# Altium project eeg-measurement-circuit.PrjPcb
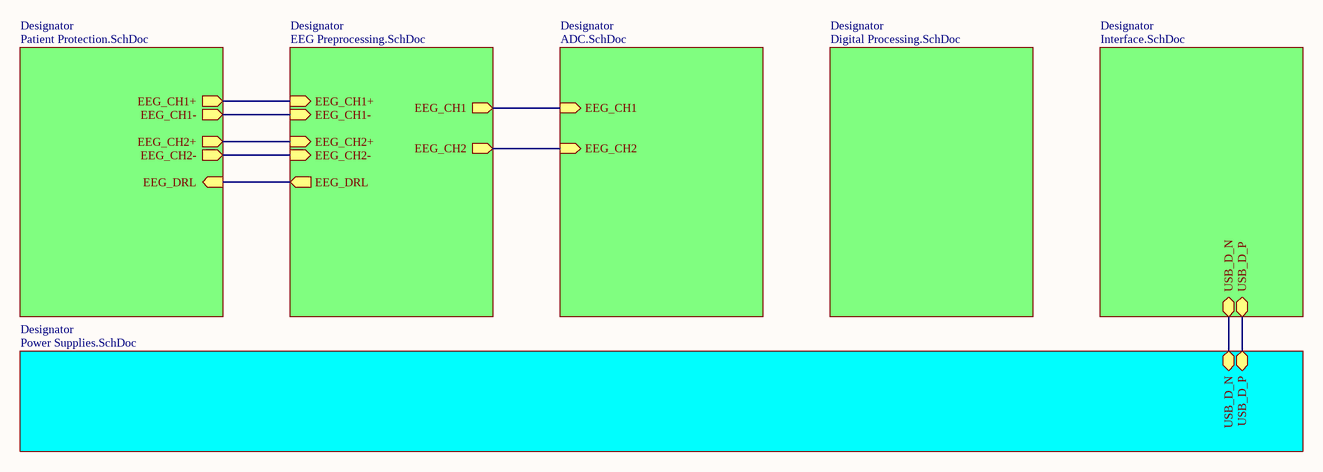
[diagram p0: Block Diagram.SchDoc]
7 sheets, 179 parts. Net scope: hierarchical (ports join the sheet entries above them; power ports are global).
Sheets:
  Block Diagram.SchDoc
    Designator = Power Supplies.SchDoc
    Designator = EEG Preprocessing.SchDoc
    Designator = ADC.SchDoc
    Designator = Digital Processing.SchDoc
    Designator = Interface.SchDoc
    Designator = Patient Protection.SchDoc

## Sheet Block Diagram.SchDoc: EEG Measurement Circuit
size A3; Date: 24/01/2025; DrawnBy: Giang Phan Truong; SheetNumber: 1; SheetTotal: 7

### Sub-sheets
Designator = Power Supplies.SchDoc: USB_D_N (bidir), USB_D_P (bidir)
Designator = EEG Preprocessing.SchDoc: EEG_CH1+ (in), EEG_CH1- (in), EEG_CH2+ (in), EEG_CH2- (in), EEG_CH1 (out), EEG_CH2 (out), EEG_DRL (out)
Designator = ADC.SchDoc: EEG_CH2 (in), EEG_CH1 (in)
Designator = Digital Processing.SchDoc: no entries
Designator = Interface.SchDoc: USB_D_P (bidir), USB_D_N (bidir)
Designator = Patient Protection.SchDoc: EEG_CH1+ (out), EEG_CH1- (out), EEG_CH2- (out), EEG_CH2+ (out), EEG_DRL (in)

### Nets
USB_D_N: sheet Designator/USB_D_N, sheet Designator/USB_D_N
USB_D_P: sheet Designator/USB_D_P, sheet Designator/USB_D_P
NetC?#17_2: sheet Designator/EEG_CH1+, sheet Designator/EEG_CH1+
NetC?#19_2: sheet Designator/EEG_CH1-, sheet Designator/EEG_CH1-
NetC?#39_2: sheet Designator/EEG_CH2+, sheet Designator/EEG_CH2+
NetC?#41_2: sheet Designator/EEG_CH2-, sheet Designator/EEG_CH2-
NetC?#56_2: sheet Designator/EEG_DRL, sheet Designator/EEG_DRL
NetR?#24_2: sheet Designator/EEG_CH1, sheet Designator/EEG_CH1
NetR?#54_2: sheet Designator/EEG_CH2, sheet Designator/EEG_CH2

## Sheet Power Supplies.SchDoc: EEG Measurement Circuit
size A3; Date: 24/01/2025; DrawnBy: Giang Phan Truong; SheetNumber: 2; SheetTotal: 7
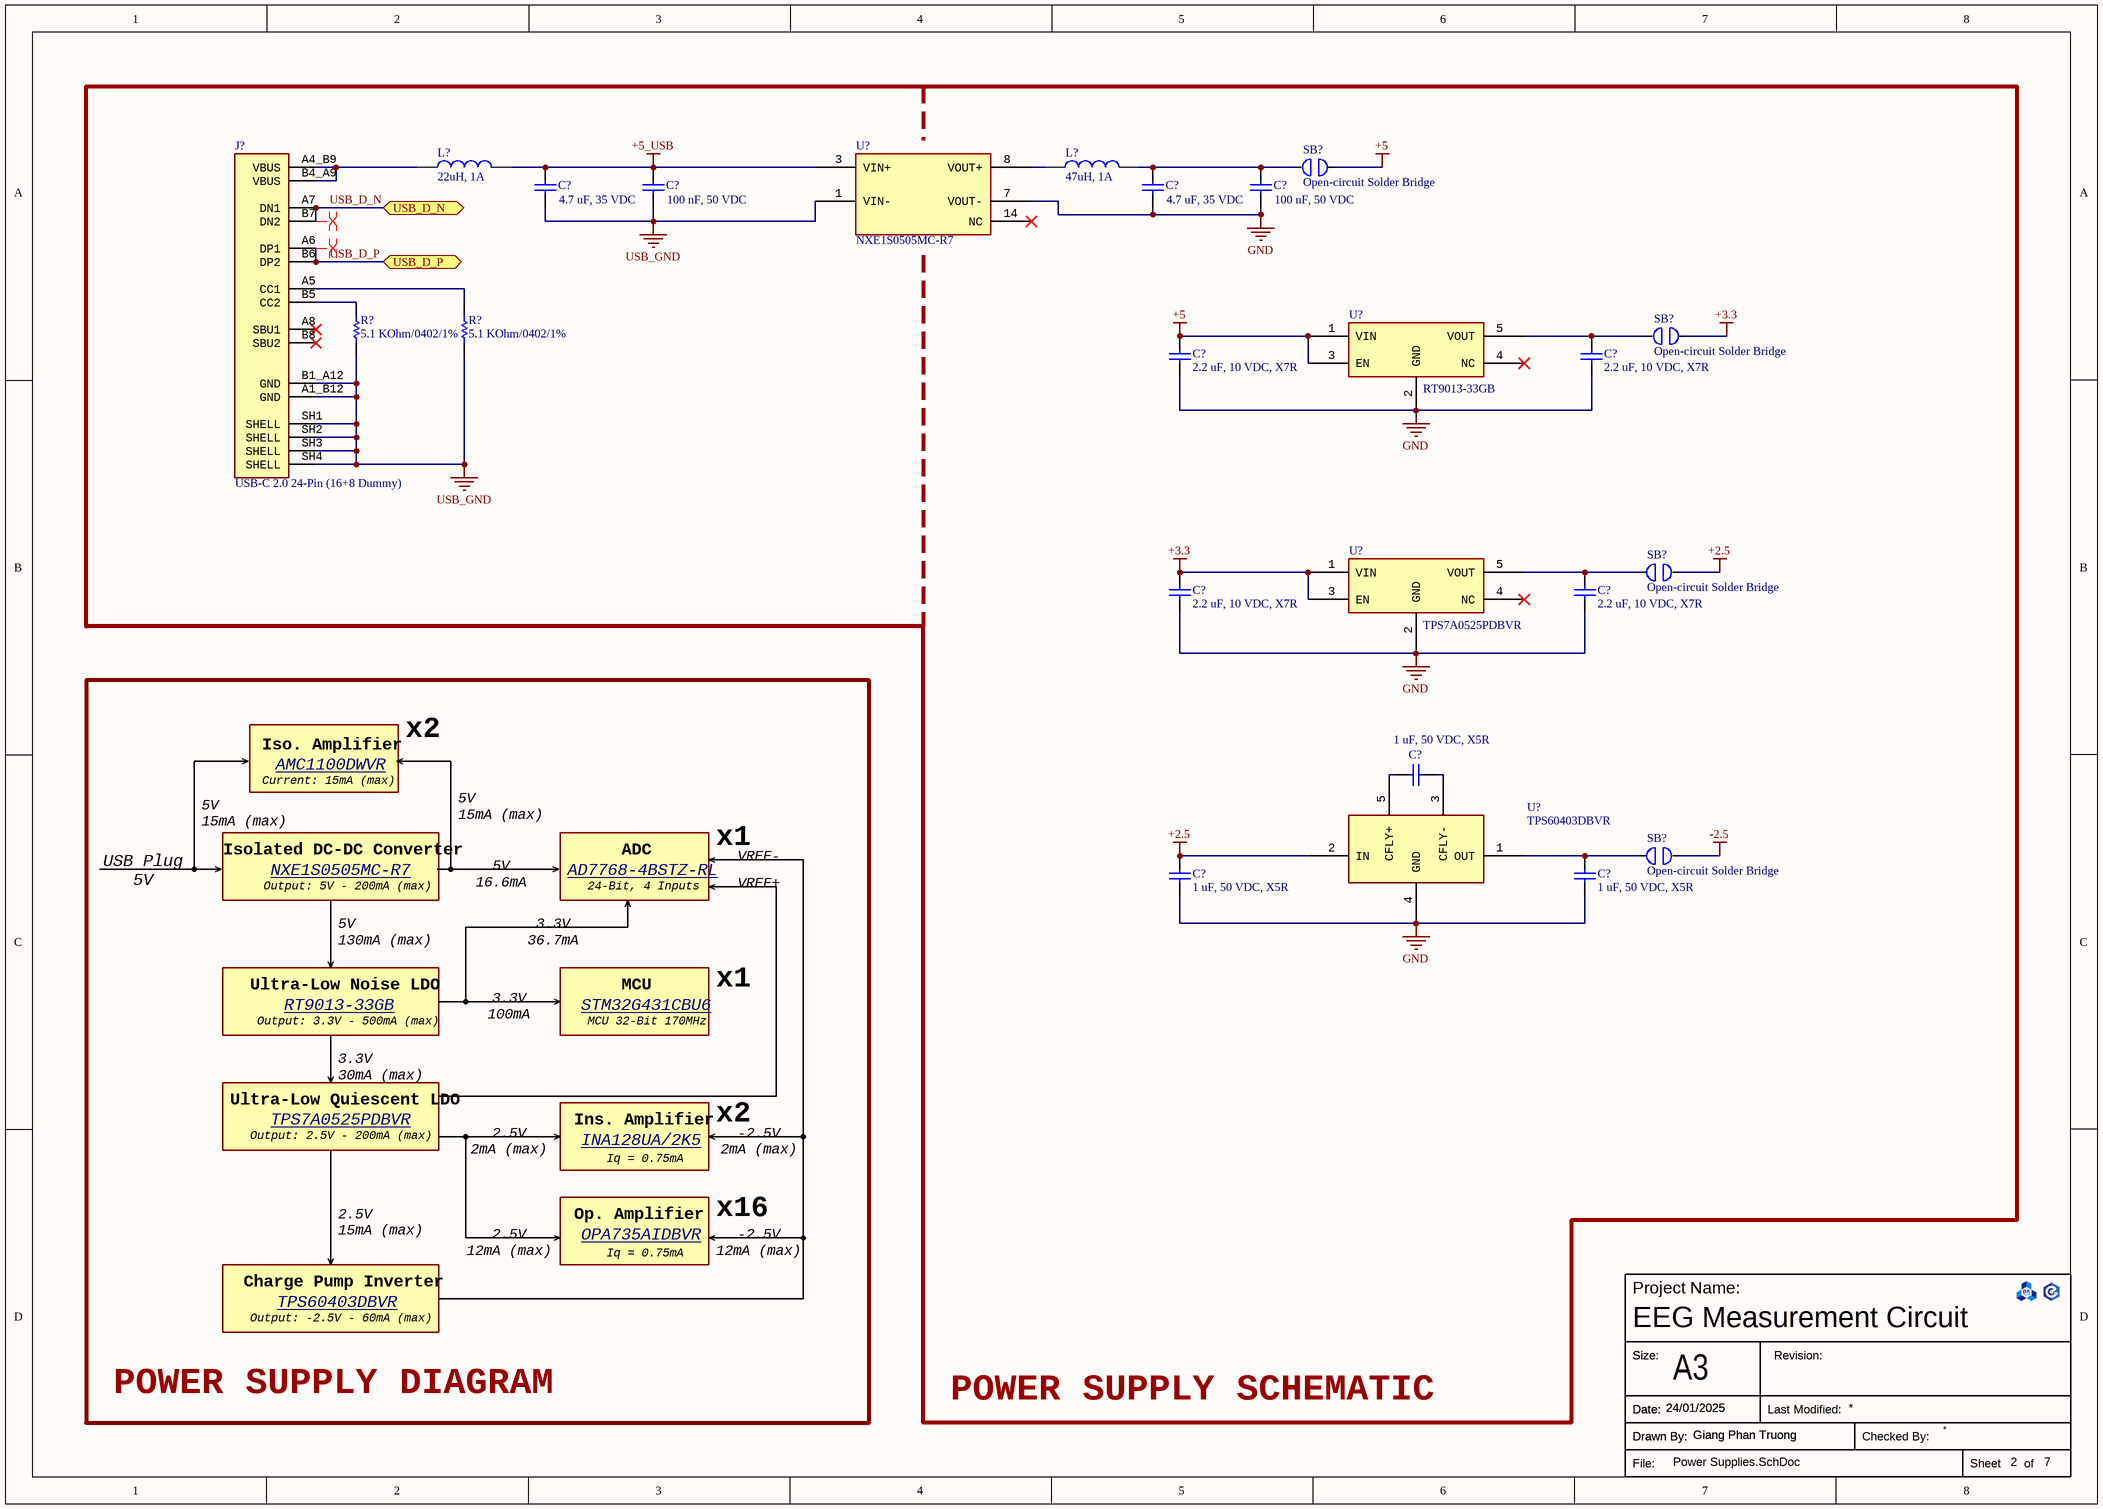
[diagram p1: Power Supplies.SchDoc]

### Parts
(Parts that share a designator on the sheet are numbered #1, #2 ... from top to bottom, then left to right.)
C?#1  4.7 uF, 35 VDC  [CAP_0603]
C?#2  100 nF, 50 VDC  [CAP_0603]
C?#3  4.7 uF, 35 VDC  [CAP_0603]
C?#4  100 nF, 50 VDC  [CAP_0603]
C?#5  2.2 uF, 10 VDC, X7R  [CAP_0603]
C?#6  2.2 uF, 10 VDC, X7R  [CAP_0603]
C?#7  2.2 uF, 10 VDC, X7R  [CAP_0603]
C?#8  2.2 uF, 10 VDC, X7R  [CAP_0603]
C?#9  1 uF, 50 VDC, X5R  [CAP_0603]
C?#10  1 uF, 50 VDC, X5R  [CAP_0603]
C?#11  1 uF, 50 VDC, X5R  [CAP_0603]
J?#1  value USB-C 2.0 24-Pin (16+8 Dummy)  [GCT_USB4105-GF-A]  (hidden comment: USB4105-GF-A)
L?#1  22uH, 1A  [Inductor_CDRH4D28]
L?#2  47uH, 1A  [Inductor_CDRH4D28]
R?#1  value 5.1 KOhm/0402/1%  [R0402]  (hidden comment: Resistor 5.1 KOhm 0402)
R?#2  value 5.1 KOhm/0402/1%  [R0402]  (hidden comment: Resistor 5.1 KOhm 0402)
SB?#1  Open-circuit Solder Bridge  [SolderBridgeOpen]
SB?#2  Open-circuit Solder Bridge  [SolderBridgeOpen]
SB?#3  Open-circuit Solder Bridge  [SolderBridgeOpen]
SB?#4  Open-circuit Solder Bridge  [SolderBridgeOpen]
U?#1  NXE1S0505MC-R7  [NXE1S0505MC_MUR]
U?#2  RT9013-33GB  [SOT-23-5_RIT]
U?#3  TPS7A0525PDBVR  [DBV0005A_L]
U?#4  TPS60403DBVR  [SOT95P280X145-5N]

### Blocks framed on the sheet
POWER SUPPLY SCHEMATIC: C?#1-C?#11 J?#1 L?#1 L?#2 R?#1 R?#2 SB?#1-SB?#4 U?#1-U?#4

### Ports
USB_D_N (bidir, see Block Diagram[7B], Interface[5B]), USB_D_P (bidir, see Block Diagram[7B], Interface[5B])

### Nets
+2.5: C?#10.2 SB?#3.1 U?#4.2(IN)
+3.3: C?#7.2 SB?#2.1 U?#3.1(VIN) U?#3.3(EN)
+5: C?#5.2 SB?#1.1 U?#2.1(VIN) U?#2.3(EN)
+5_USB: C?#1.2 C?#2.2 L?#1.2 U?#1.3(VIN+)
-2.5: SB?#4.1
GND: C?#3.1 C?#4.1 C?#5.1 C?#6.1 C?#7.1 C?#8.1 C?#10.1 C?#11.1 U?#1.7(VOUT-) U?#2.2(GND) U?#3.2(GND) U?#4.4(GND)
USB_GND: C?#1.1 C?#2.1 J?#1.A1_B12(GND) J?#1.B1_A12(GND) J?#1.SH1(SHELL) J?#1.SH2(SHELL) J?#1.SH3(SHELL) J?#1.SH4(SHELL) R?#1.1 R?#2.1 U?#1.1(VIN-)
USB_D_N: J?#1.A7(DN1) J?#1.B7(DN2) ; port USB_D_N
USB_D_P: J?#1.A6(DP1) J?#1.B6(DP2) ; port USB_D_P
NetC?#3_2: C?#3.2 C?#4.2 L?#2.2 SB?#1.2
NetC?#6_2: C?#6.2 SB?#2.2 U?#2.5(VOUT)
NetC?#8_2: C?#8.2 SB?#3.2 U?#3.5(VOUT)
NetC?#9_1: C?#9.1 U?#4.5(CFLY+)
NetC?#9_2: C?#9.2 U?#4.3(CFLY-)
NetC?#11_2: C?#11.2 SB?#4.2 U?#4.1(OUT)
NetJ?#1_A4_B9: J?#1.A4_B9(VBUS) J?#1.B4_A9(VBUS) L?#1.1
NetJ?#1_A5: J?#1.A5(CC1) R?#2.2
NetJ?#1_B5: J?#1.B5(CC2) R?#1.2
NetL?#2_1: L?#2.1 U?#1.8(VOUT+)

Not connected (* = marked no-connect by the designer): J?#1 A8(SBU1)* B8(SBU2)*; U?#1 14(NC)*; U?#2 4(NC)*; U?#3 4(NC)*

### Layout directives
differential pair: USB_D_N, USB_D_P

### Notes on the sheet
- Iso. Amplifier
- Current: 15mA (max)
- AMC1100DWVR <https://www.digikey.com/en/products/detail/texas-instruments/amc1100dwvr/6571602>
- x2
- 5V
  15mA (max)
- Isolated DC-DC Converter
- ADC
- x1
- USB Plug
  5V
- Output: 5V - 200mA (max)
- NXE1S0505MC-R7 <https://www.digikey.com/en/products/detail/murata-power-solutions-inc/NXE1S0505MC-R7/5047366>
- 5V
  16.6mA (max)
- AD7768-4BSTZ-RL <https://www.digikey.com/en/products/detail/analog-devices-inc/AD7768-4BSTZ-RL/6056981>
- 24-Bit, 4 Inputs
- VREF-
- VREF+
- Ultra-Low Noise LDO
- 5V
  130mA (max)
- 3.3V
  36.7mA (max)
- MCU
- Output: 3.3V - 500mA (max)
- RT9013-33GB <https://www.thegioiic.com/rt9013-33gb-ic-on-ap-3-3v-500ma-sot-23-5>
- 3.3V
  100mA (max)
- STM32G431CBU6 <https://www.digikey.com/en/products/detail/stmicroelectronics/STM32G431CBU6/10231569>
- MCU 32-Bit 170MHz
- Ultra-Low Quiescent LDO
- TPS7A0525PDBVR <https://www.digikey.com/en/products/detail/texas-instruments/TPS7A0525PDBVR/9489224>
- 3.3V
  30mA (max)
- Ins. Amplifier
- Output: 2.5V - 200mA (max)
- 2.5V
  2mA (max)
- INA128UA/2K5 <https://www.digikey.com/en/products/detail/texas-instruments/INA128UA-2K5/300998>
- Iq = 0.75mA
- -2.5V
  2mA (max)
- 2.5V
  15mA (max)
- 2.5V
  12mA (max)
- Op. Amplifier
- OPA735AIDBVR <https://www.digikey.com/en/products/detail/texas-instruments/OPA735AIDBVR/1572946>
- x16
- -2.5V
  12mA (max)
- Charge Pump Inverter
- Output: -2.5V - 60mA (max)
- TPS60403DBVR <https://www.digikey.com/en/products/detail/texas-instruments/TPS60403DBVR/1672064>
- POWER SUPPLY DIAGRAM

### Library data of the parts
C?#1 C?#3 = 0106034751035: CAP, size 0603, 4.7 uF, 35 VDC; Manufacture Name: Samsung Electro-Mechanics; Manufacture SN: CL10A475KL8NRNC; Capacitance: 4.7 uF; Tolerance: +/-10%; Voltage Rating DC: 35 VDC
C?#2 C?#4 = 0106031041050: CAP, size 0603, 100 nF, 50 VDC; Manufacture Name: TDK; Manufacture SN: CGA3E3X8R1H104K080AE; Capacitance: 100 nF; Tolerance: +/-10%; Voltage Rating DC: 50 VDC
C?#5-C?#8 = 0106032251010: CAP, size 0603, 2.2 uF, 10 VDC; Manufacture Name: Samsung Electro-Mechanics; Manufacture SN: CL10A225KP8NNWC; Capacitance: 2.2 uF; Tolerance: +/-10%; Voltage Rating DC: 10 VDC
C?#9-C?#11 = 0106031051050: CAP, size 0603, 1 nF, 50 VDC; Manufacture Name: TDK; Manufacture SN: CGA3E3X5R1H105K080AB; Capacitance: 1 nF; Tolerance: +/-10%; Voltage Rating DC: 50 VDC
J?#1 = USB4105-GF-A: USB-C (USB TYPE-C) USB 2.0 Receptacle Connector 24 (16+8 Dummy) Position Surface Mount, Right Angle; Through Hole; MF: {'manufacturer': u'GCT'}
L?#1 = IND_22uH_4D28: 22uH 20% 1A SMD Power Inductor 4.8x4.8x2.8 mm; Supply Name: tme
L?#2 = IND_47uH_4D28: 47uH 20% 1A SMD Power Inductor 4.8x4.8x2.8 mm; Supply Part Number: 22uH 20% 1A SMD Power Inductor 4.8x4.8x2.8 mm; Supply Name: tme
R?#1 R?#2 = Resistor 5.1 KOhm 0402: RC0402FR-135K1L
U?#1 = NXE1S0505MC-R7: Isolated Module DC DC Converter 1 Output 5V 200mA 4.5V - 5.5V Input; Mfr_Name: Murata
U?#2 = RT9013-33GB: Linear Voltage Regulator IC Positive Fixed 1 Output 500mA SOT-23-5; Mfr_Name: Richtek Technology
U?#3 = TPS7A0525PDBVR: Linear Voltage Regulator IC Positive Fixed 1 Output 200mA SOT-23-5; Mfr_Name: Texas Instruments
U?#4 = TPS60403DBVR: 60mA Charge Pump Voltage Inverter with Fixed 250kHz Operation; MF: Texas Instruments

## Sheet EEG Preprocessing.SchDoc: EEG Measurement Circuit
size A2; Date: 24/01/2025; DrawnBy: Giang Phan Truong; SheetNumber: 4; SheetTotal: 7; SPICEModelCacheZASXATAV: <root> / <DocumentId>ZASXATAV</DocumentId> / <CacheFrame Number="0"> / <Model Name="0402_885012105018_100nf" Kind="CKT"> / <Text>******* / .subckt 0402_885012105018_100nF 1 2 / Rser 1 3 0.026120802334 / Lser 2 4 3.09671131E-10 / C1 3 4 0.0000001 / Rpar 3 4 5000000000 / .ends 0402_885012105018_100nF</Text> / </Model> / <Model Name="0402_885012105017_220nf" Kind="CKT"> / <Text>******* / .subckt 0402_885012105017_220nF 1 2 / Rser 1 3 0.0118013539585 / Lser 2 4 3.47460059E-10 / C1 3 4 0.00000022 / Rpar 3 4 500000000 / .ends 0402_885012105017_220nF</Text> / </Model> / <Model Name="1812_885012210006_10nf" Kind="CKT"> / <Text>******* / .subckt 1812_885012210006_10nF 1 2 / Rser 1 3 0.07693 / Lser 2 4 0.00000000053548 / C1 3 4 0.00000001 / Rpar 3 4 10000000000 / .ends 1812_885012210006_10nF</Text> / </Model> / </CacheFrame> / </root>
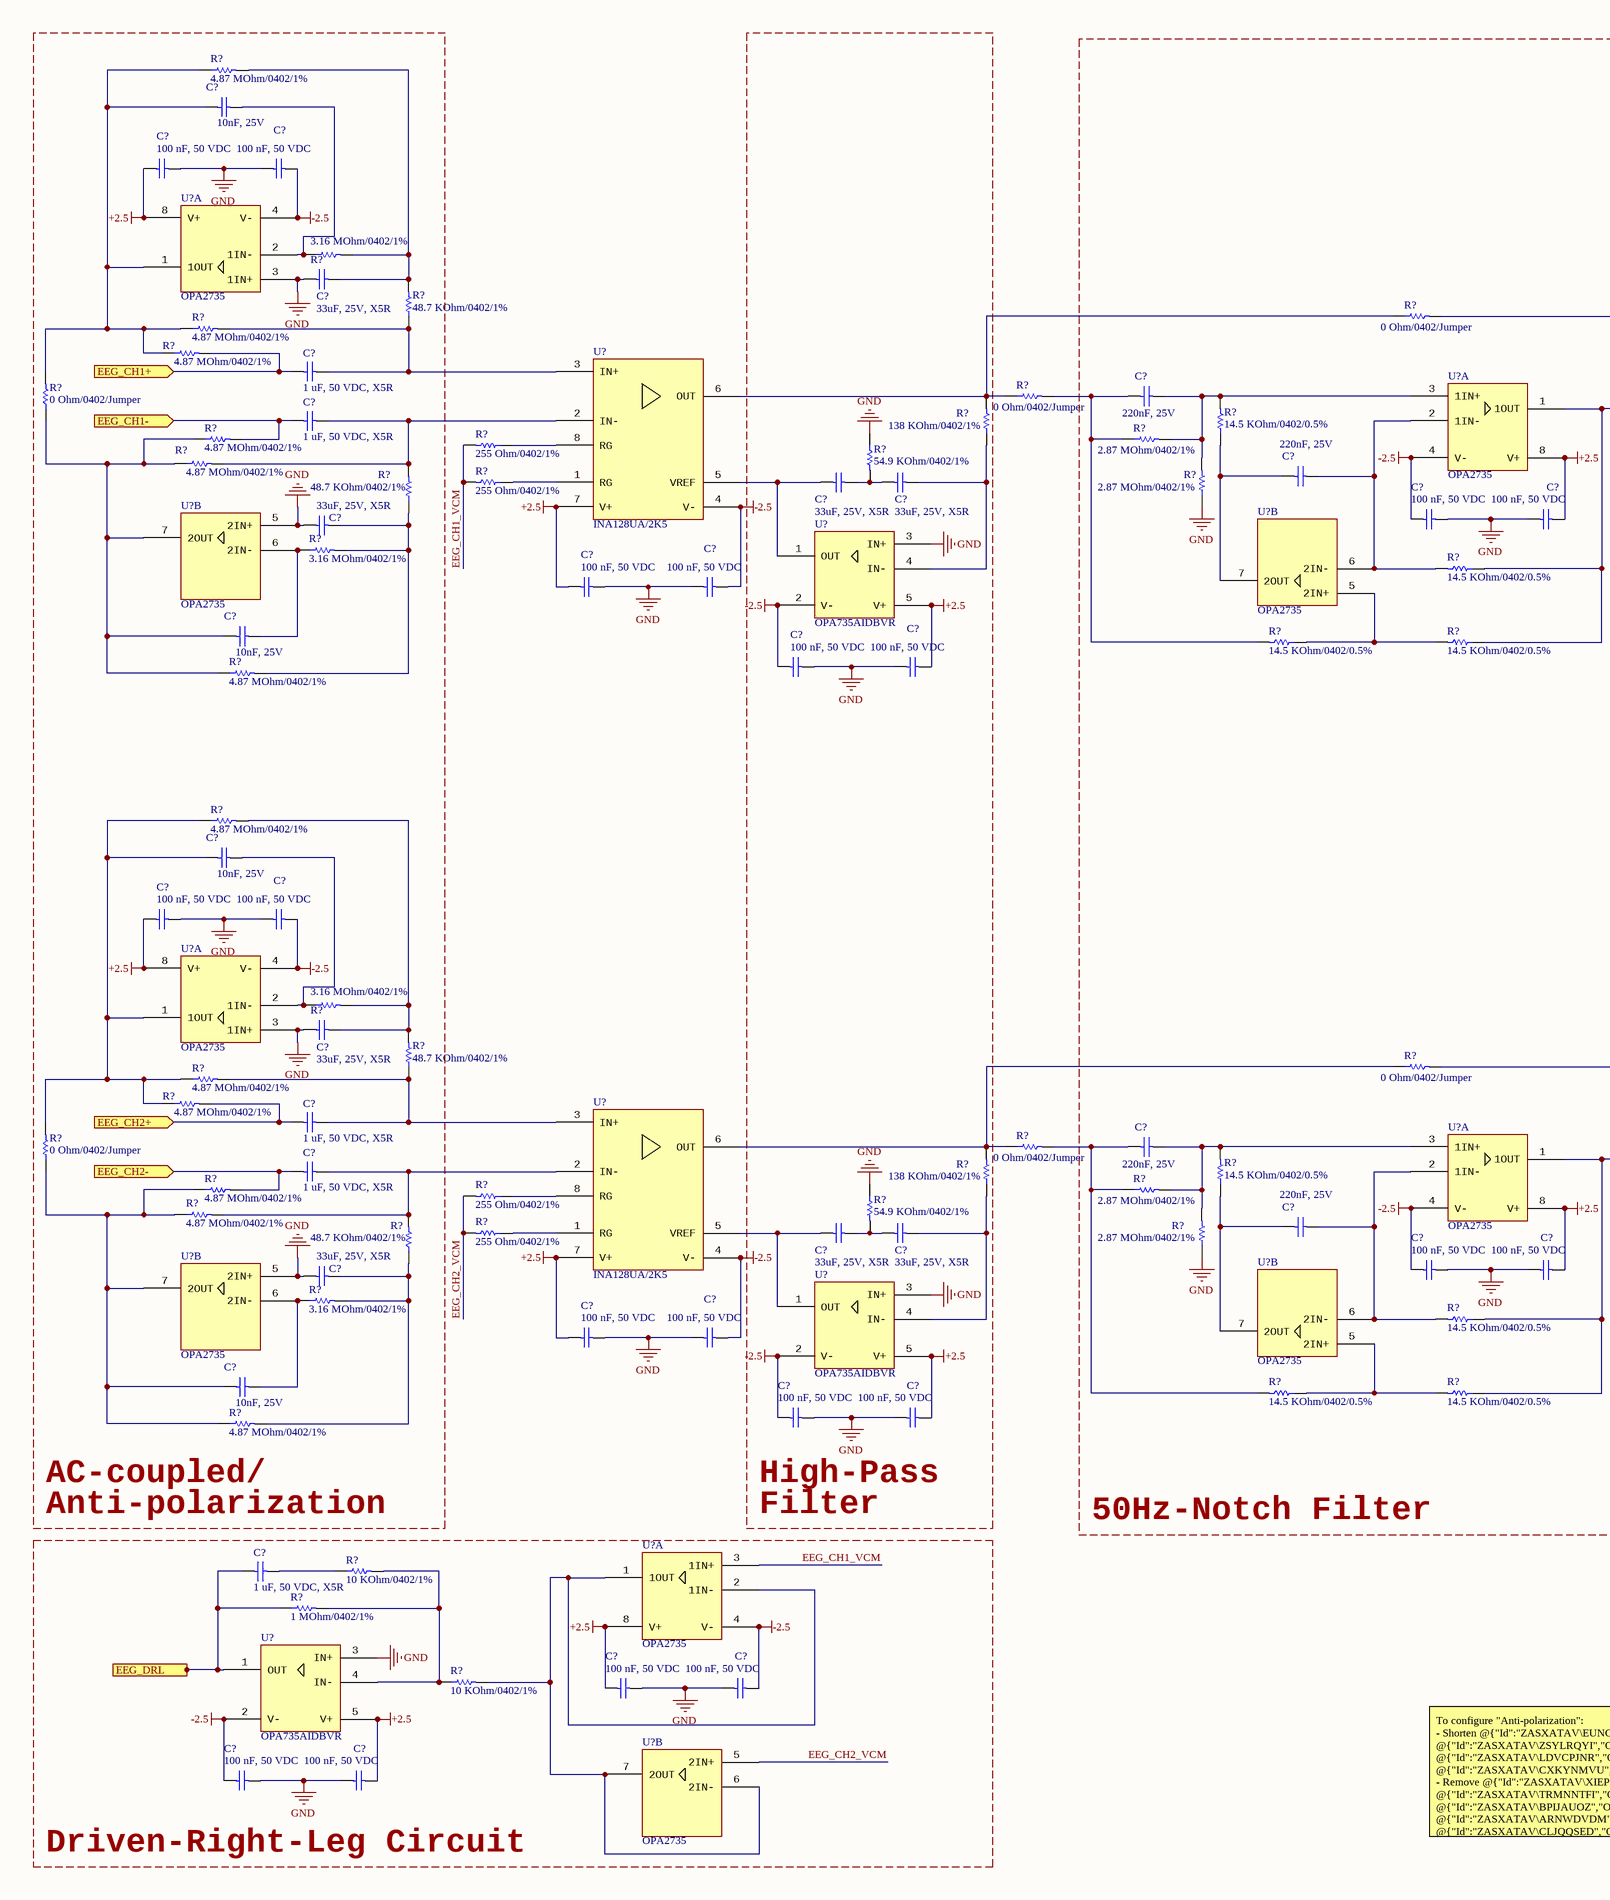
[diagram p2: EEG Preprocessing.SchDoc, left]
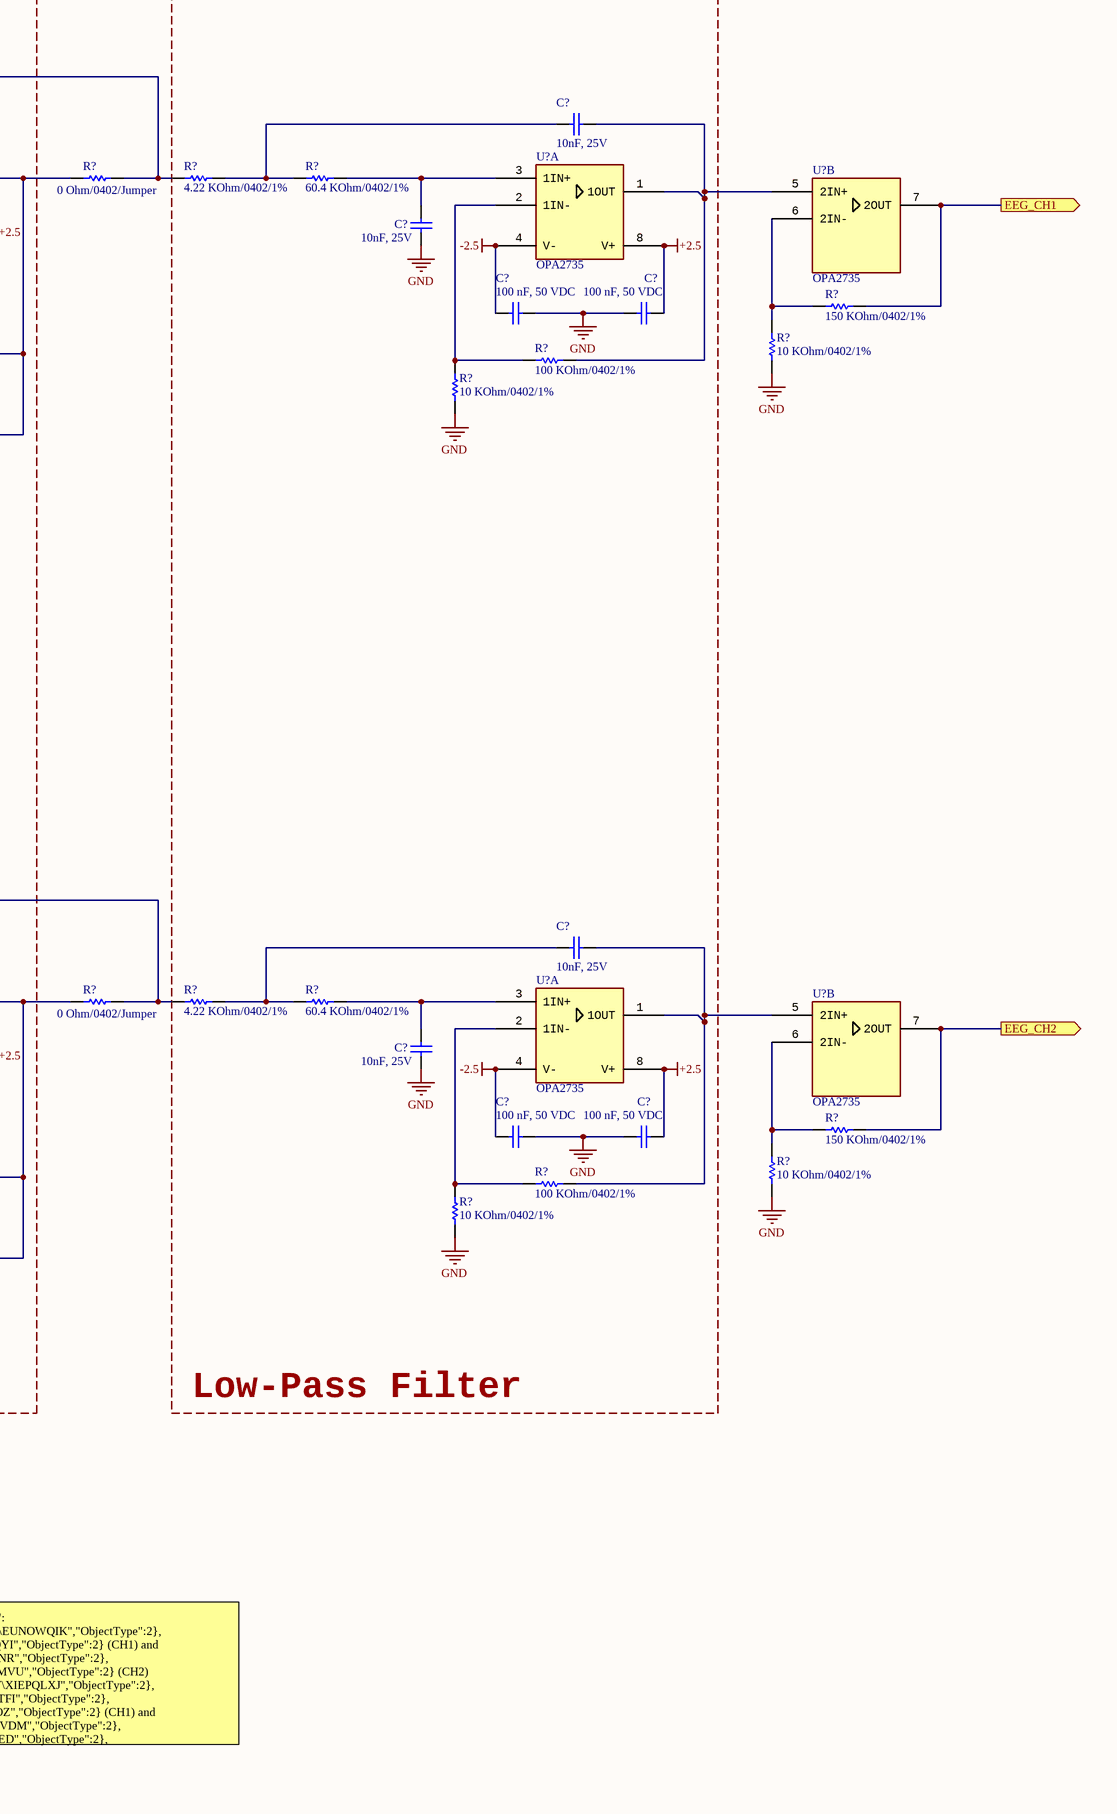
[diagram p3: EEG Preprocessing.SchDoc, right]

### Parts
(Parts that share a designator on the sheet are numbered #1, #2 ... from top to bottom, then left to right.)
C?#12  value 10nF, 25V  [WCAP-CSGP_0402_L1W0.5H0.5]  (hidden comment: 100nF)
C?#13  100 nF, 50 VDC  [CAP_0603]
C?#14  100 nF, 50 VDC  [CAP_0603]
C?#15  value 33uF, 25V, X5R  [WCAP-CSGP_1206_L3.2W1.6H1.6]  (hidden comment: 4.7μF)
C?#16  value 10nF, 25V  [WCAP-CSGP_1812_L4.5W3.2H1.25]  (hidden comment: 10nF)
C?#17  1 uF, 50 VDC, X5R  [CAP_0603]
C?#18  value 220nF, 25V  [WCAP-CSGP_0402_L1W0.5H0.5]  (hidden comment: 220nF)
C?#19  1 uF, 50 VDC, X5R  [CAP_0603]
C?#20  value 10nF, 25V  [WCAP-CSGP_1812_L4.5W3.2H1.25]  (hidden comment: 10nF)
C?#21  value 220nF, 25V  [WCAP-CSGP_0402_L1W0.5H0.5]  (hidden comment: 220nF)
C?#22  value 33uF, 25V, X5R  [WCAP-CSGP_1206_L3.2W1.6H1.6]  (hidden comment: 4.7μF)
C?#23  value 33uF, 25V, X5R  [WCAP-CSGP_1206_L3.2W1.6H1.6]  (hidden comment: 4.7μF)
C?#24  100 nF, 50 VDC  [CAP_0603]
C?#25  100 nF, 50 VDC  [CAP_0603]
C?#26  value 33uF, 25V, X5R  [WCAP-CSGP_1206_L3.2W1.6H1.6]  (hidden comment: 4.7μF)
C?#27  100 nF, 50 VDC  [CAP_0603]
C?#28  100 nF, 50 VDC  [CAP_0603]
C?#29  100 nF, 50 VDC  [CAP_0603]
C?#30  100 nF, 50 VDC  [CAP_0603]
C?#31  value 10nF, 25V  [WCAP-CSGP_0402_L1W0.5H0.5]  (hidden comment: 100nF)
C?#32  100 nF, 50 VDC  [CAP_0603]
C?#33  100 nF, 50 VDC  [CAP_0603]
C?#34  value 10nF, 25V  [WCAP-CSGP_0402_L1W0.5H0.5]  (hidden comment: 100nF)
C?#35  100 nF, 50 VDC  [CAP_0603]
C?#36  100 nF, 50 VDC  [CAP_0603]
C?#37  value 33uF, 25V, X5R  [WCAP-CSGP_1206_L3.2W1.6H1.6]  (hidden comment: 4.7μF)
C?#38  value 10nF, 25V  [WCAP-CSGP_1812_L4.5W3.2H1.25]  (hidden comment: 10nF)
C?#39  1 uF, 50 VDC, X5R  [CAP_0603]
C?#40  value 220nF, 25V  [WCAP-CSGP_0402_L1W0.5H0.5]  (hidden comment: 220nF)
C?#41  1 uF, 50 VDC, X5R  [CAP_0603]
C?#42  value 10nF, 25V  [WCAP-CSGP_1812_L4.5W3.2H1.25]  (hidden comment: 10nF)
C?#43  value 220nF, 25V  [WCAP-CSGP_0402_L1W0.5H0.5]  (hidden comment: 220nF)
C?#44  value 33uF, 25V, X5R  [WCAP-CSGP_1206_L3.2W1.6H1.6]  (hidden comment: 4.7μF)
C?#45  value 33uF, 25V, X5R  [WCAP-CSGP_1206_L3.2W1.6H1.6]  (hidden comment: 4.7μF)
C?#46  100 nF, 50 VDC  [CAP_0603]
C?#47  100 nF, 50 VDC  [CAP_0603]
C?#48  value 33uF, 25V, X5R  [WCAP-CSGP_1206_L3.2W1.6H1.6]  (hidden comment: 4.7μF)
C?#49  100 nF, 50 VDC  [CAP_0603]
C?#50  100 nF, 50 VDC  [CAP_0603]
C?#51  100 nF, 50 VDC  [CAP_0603]
C?#52  100 nF, 50 VDC  [CAP_0603]
C?#53  value 10nF, 25V  [WCAP-CSGP_0402_L1W0.5H0.5]  (hidden comment: 100nF)
C?#54  100 nF, 50 VDC  [CAP_0603]
C?#55  100 nF, 50 VDC  [CAP_0603]
C?#56  1 uF, 50 VDC, X5R  [CAP_0603]
C?#57  100 nF, 50 VDC  [CAP_0603]
C?#58  100 nF, 50 VDC  [CAP_0603]
C?#59  100 nF, 50 VDC  [CAP_0603]
C?#60  100 nF, 50 VDC  [CAP_0603]
R?#3  value 4.87 MOhm/0402/1%  [R0402]  (hidden comment: Resistor 4.87 MOhm 0402 1%)
R?#4  value 3.16 MOhm/0402/1%  [R0402]  (hidden comment: Resistor 3.16 MOhm 0402 1%)
R?#5  value 48.7 KOhm/0402/1%  [R0402]  (hidden comment: Resistor 48.7 KOhm 0402 1%)
R?#6  value 0 Ohm/0402/Jumper  [R0402]  (hidden comment: Resistor 0 Ohm 0402)
R?#7  value 4.87 MOhm/0402/1%  [R0402]  (hidden comment: Resistor 4.87 MOhm 0402 1%)
R?#8  value 4.87 MOhm/0402/1%  [R0402]  (hidden comment: Resistor 4.87 MOhm 0402 1%)
R?#9  value 0 Ohm/0402/Jumper  [R0402]  (hidden comment: Resistor 0 Ohm 0402)
R?#10  value 0 Ohm/0402/Jumper  [R0402]  (hidden comment: Resistor 0 Ohm 0402)
R?#11  value 0 Ohm/0402/Jumper  [R0402]  (hidden comment: Resistor 0 Ohm 0402)
R?#12  value 4.22 KOhm/0402/1%  [R0402]  (hidden comment: Resistor 4.22 KOhm 0402 1%)
R?#13  value 60.4 KOhm/0402/1%  [R0402]  (hidden comment: Resistor 60.4 KOhm 0402 1%)
R?#14  value 138 KOhm/0402/1%  [R0402]  (hidden comment: Resistor 138 KOhm 0402 1%)
R?#15  value 14.5 KOhm/0402/0.5%  [R0402]  (hidden comment: Resistor 14.5 KOhm 0402 0.5%)
R?#16  value 4.87 MOhm/0402/1%  [R0402]  (hidden comment: Resistor 4.87 MOhm 0402 1%)
R?#17  value 2.87 MOhm/0402/1%  [R0402]  (hidden comment: Resistor 2.87 MOhm 0402 1%)
R?#18  value 255 Ohm/0402/1%  [R0402]  (hidden comment: Resistor 255 Ohm 0402 1%)
R?#19  value 54.9 KOhm/0402/1%  [R0402]  (hidden comment: Resistor 54.9 KOhm 0402 1%)
R?#20  value 4.87 MOhm/0402/1%  [R0402]  (hidden comment: Resistor 4.87 MOhm 0402 1%)
R?#21  value 255 Ohm/0402/1%  [R0402]  (hidden comment: Resistor 255 Ohm 0402 1%)
R?#22  value 2.87 MOhm/0402/1%  [R0402]  (hidden comment: Resistor 2.87 MOhm 0402 1%)
R?#23  value 48.7 KOhm/0402/1%  [R0402]  (hidden comment: Resistor 48.7 KOhm 0402 1%)
R?#24  value 150 KOhm/0402/1%  [R0402]  (hidden comment: Resistor 150 KOhm 0402 1%)
R?#25  value 3.16 MOhm/0402/1%  [R0402]  (hidden comment: Resistor 3.16 MOhm 0402 1%)
R?#26  value 10 KOhm/0402/1%  [R0402]  (hidden comment: Resistor 10 KOhm 0402 1%)
R?#27  value 14.5 KOhm/0402/0.5%  [R0402]  (hidden comment: Resistor 14.5 KOhm 0402 0.5%)
R?#28  value 100 KOhm/0402/1%  [R0402]  (hidden comment: Resistor 100 KOhm 0402 1%)
R?#29  value 10 KOhm/0402/1%  [R0402]  (hidden comment: Resistor 10 KOhm 0402 1%)
R?#30  value 14.5 KOhm/0402/0.5%  [R0402]  (hidden comment: Resistor 14.5 KOhm 0402 0.5%)
R?#31  value 14.5 KOhm/0402/0.5%  [R0402]  (hidden comment: Resistor 14.5 KOhm 0402 0.5%)
R?#32  value 4.87 MOhm/0402/1%  [R0402]  (hidden comment: Resistor 4.87 MOhm 0402 1%)
R?#33  value 4.87 MOhm/0402/1%  [R0402]  (hidden comment: Resistor 4.87 MOhm 0402 1%)
R?#34  value 3.16 MOhm/0402/1%  [R0402]  (hidden comment: Resistor 3.16 MOhm 0402 1%)
R?#35  value 48.7 KOhm/0402/1%  [R0402]  (hidden comment: Resistor 48.7 KOhm 0402 1%)
R?#36  value 0 Ohm/0402/Jumper  [R0402]  (hidden comment: Resistor 0 Ohm 0402)
R?#37  value 4.87 MOhm/0402/1%  [R0402]  (hidden comment: Resistor 4.87 MOhm 0402 1%)
R?#38  value 4.87 MOhm/0402/1%  [R0402]  (hidden comment: Resistor 4.87 MOhm 0402 1%)
R?#39  value 0 Ohm/0402/Jumper  [R0402]  (hidden comment: Resistor 0 Ohm 0402)
R?#40  value 0 Ohm/0402/Jumper  [R0402]  (hidden comment: Resistor 0 Ohm 0402)
R?#41  value 0 Ohm/0402/Jumper  [R0402]  (hidden comment: Resistor 0 Ohm 0402)
R?#42  value 4.22 KOhm/0402/1%  [R0402]  (hidden comment: Resistor 4.22 KOhm 0402 1%)
R?#43  value 60.4 KOhm/0402/1%  [R0402]  (hidden comment: Resistor 60.4 KOhm 0402 1%)
R?#44  value 138 KOhm/0402/1%  [R0402]  (hidden comment: Resistor 138 KOhm 0402 1%)
R?#45  value 14.5 KOhm/0402/0.5%  [R0402]  (hidden comment: Resistor 14.5 KOhm 0402 0.5%)
R?#46  value 4.87 MOhm/0402/1%  [R0402]  (hidden comment: Resistor 4.87 MOhm 0402 1%)
R?#47  value 2.87 MOhm/0402/1%  [R0402]  (hidden comment: Resistor 2.87 MOhm 0402 1%)
R?#48  value 255 Ohm/0402/1%  [R0402]  (hidden comment: Resistor 255 Ohm 0402 1%)
R?#49  value 54.9 KOhm/0402/1%  [R0402]  (hidden comment: Resistor 54.9 KOhm 0402 1%)
R?#50  value 4.87 MOhm/0402/1%  [R0402]  (hidden comment: Resistor 4.87 MOhm 0402 1%)
R?#51  value 255 Ohm/0402/1%  [R0402]  (hidden comment: Resistor 255 Ohm 0402 1%)
R?#52  value 2.87 MOhm/0402/1%  [R0402]  (hidden comment: Resistor 2.87 MOhm 0402 1%)
R?#53  value 48.7 KOhm/0402/1%  [R0402]  (hidden comment: Resistor 48.7 KOhm 0402 1%)
R?#54  value 150 KOhm/0402/1%  [R0402]  (hidden comment: Resistor 150 KOhm 0402 1%)
R?#55  value 3.16 MOhm/0402/1%  [R0402]  (hidden comment: Resistor 3.16 MOhm 0402 1%)
R?#56  value 10 KOhm/0402/1%  [R0402]  (hidden comment: Resistor 10 KOhm 0402 1%)
R?#57  value 14.5 KOhm/0402/0.5%  [R0402]  (hidden comment: Resistor 14.5 KOhm 0402 0.5%)
R?#58  value 100 KOhm/0402/1%  [R0402]  (hidden comment: Resistor 100 KOhm 0402 1%)
R?#59  value 10 KOhm/0402/1%  [R0402]  (hidden comment: Resistor 10 KOhm 0402 1%)
R?#60  value 14.5 KOhm/0402/0.5%  [R0402]  (hidden comment: Resistor 14.5 KOhm 0402 0.5%)
R?#61  value 14.5 KOhm/0402/0.5%  [R0402]  (hidden comment: Resistor 14.5 KOhm 0402 0.5%)
R?#62  value 4.87 MOhm/0402/1%  [R0402]  (hidden comment: Resistor 4.87 MOhm 0402 1%)
R?#63  value 10 KOhm/0402/1%  [R0402]  (hidden comment: Resistor 10 KOhm 0402 1%)
R?#64  value 1 MOhm/0402/1%  [R0402]  (hidden comment: Resistor 1 MOhm 0402 1%_1)
R?#65  value 10 KOhm/0402/1%  [R0402]  (hidden comment: Resistor 10 KOhm 0402 1%)
U?#5  value OPA2735  [SOIC-8]  (hidden comment: OPA2735AIDR)  (part A of 2)
U?#6  INA128UA/2K5  [SOIC-8]
U?#7  value OPA2735  [SOIC-8]  (hidden comment: OPA2735AIDR)  (part A of 2)
U?#8  value OPA2735  [SOIC-8]  (hidden comment: OPA2735AIDR)  (part A of 2)
U?#9  value OPA2735  [SOIC-8]  (hidden comment: OPA2735AIDR)  (part B of 2)
U?#10  OPA735AIDBVR  [SOT-23]
U?#11  value OPA2735  [SOIC-8]  (hidden comment: OPA2735AIDR)  (part B of 2)
U?#12  value OPA2735  [SOIC-8]  (hidden comment: OPA2735AIDR)  (part B of 2)
U?#13  value OPA2735  [SOIC-8]  (hidden comment: OPA2735AIDR)  (part A of 2)
U?#14  INA128UA/2K5  [SOIC-8]
U?#15  value OPA2735  [SOIC-8]  (hidden comment: OPA2735AIDR)  (part A of 2)
U?#16  value OPA2735  [SOIC-8]  (hidden comment: OPA2735AIDR)  (part A of 2)
U?#17  value OPA2735  [SOIC-8]  (hidden comment: OPA2735AIDR)  (part B of 2)
U?#18  OPA735AIDBVR  [SOT-23]
U?#19  value OPA2735  [SOIC-8]  (hidden comment: OPA2735AIDR)  (part B of 2)
U?#20  value OPA2735  [SOIC-8]  (hidden comment: OPA2735AIDR)  (part B of 2)
U?#21  value OPA2735  [SOIC-8]  (hidden comment: OPA2735AIDR)  (part A of 2)
U?#22  OPA735AIDBVR  [SOT-23]
U?#23  value OPA2735  [SOIC-8]  (hidden comment: OPA2735AIDR)  (part B of 2)

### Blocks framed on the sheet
50Hz-Notch Filter: C?#18 C?#21 C?#24 C?#25 C?#40 C?#43 C?#46 C?#47 R?#6 R?#15 R?#17 R?#22 R?#27 R?#30 R?#31 R?#36 R?#45 R?#47 R?#52 R?#57 R?#60 R?#61 U?#7 U?#12 U?#15 U?#20
Low-Pass Filter: C?#16 C?#20 C?#27 C?#28 C?#38 C?#42 C?#49 C?#50 R?#12 R?#13 R?#28 R?#29 R?#42 R?#43 R?#58 R?#59 U?#8 U?#16
Driven-Right-Leg Circuit: C?#56-C?#60 R?#63-R?#65 U?#21-U?#23

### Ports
EEG_CH1 (out, see Block Diagram[4B], ADC[1B]), EEG_CH1+ (in, see Block Diagram[3B], Patient Protection[6A]), EEG_CH1- (in, see Block Diagram[3B], Patient Protection[6B]), EEG_CH2 (out, see Block Diagram[4B], ADC[1B]), EEG_CH2+ (in, see Block Diagram[3B], Patient Protection[6B]), EEG_CH2- (in, see Block Diagram[3B], Patient Protection[6C]), EEG_DRL (out, see Block Diagram[3B], Patient Protection[4D])

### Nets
+2.5: C?#13.2 C?#25.1 C?#28.1 C?#29.2 C?#33.1 C?#35.2 C?#47.1 C?#50.1 C?#51.2 C?#55.1 C?#57.2 C?#60.1 U?#5.8(V+) U?#6.7(V+) U?#7.8(V+) U?#8.8(V+) U?#10.5(V+) U?#13.8(V+) U?#14.7(V+) U?#15.8(V+) U?#16.8(V+) U?#18.5(V+) U?#21.8(V+) U?#22.5(V+)
-2.5: C?#14.1 C?#24.2 C?#27.2 C?#30.1 C?#32.2 C?#36.1 C?#46.2 C?#49.2 C?#52.1 C?#54.2 C?#58.1 C?#59.2 U?#5.4(V-) U?#6.4(V-) U?#7.4(V-) U?#8.4(V-) U?#10.2(V-) U?#13.4(V-) U?#14.4(V-) U?#15.4(V-) U?#16.4(V-) U?#18.2(V-) U?#21.4(V-) U?#22.2(V-)
GND: C?#13.1 C?#14.2 C?#15.2 C?#20.1 C?#24.1 C?#25.2 C?#26.2 C?#27.1 C?#28.2 C?#29.1 C?#30.2 C?#32.1 C?#33.2 C?#35.1 C?#36.2 C?#37.2 C?#42.1 C?#46.1 C?#47.2 C?#48.2 C?#49.1 C?#50.2 C?#51.1 C?#52.2 C?#54.1 C?#55.2 C?#57.1 C?#58.2 C?#59.1 C?#60.2 R?#19.1 R?#22.1 R?#26.1 R?#29.1 R?#49.1 R?#52.1 R?#56.1 R?#59.1 U?#5.3(1IN+) U?#10.3(IN+) U?#11.5(2IN+) U?#13.3(1IN+) U?#18.3(IN+) U?#19.5(2IN+) U?#22.3(IN+)
EEG_CH1_VCM: R?#18.2 R?#21.2 U?#21.3(1IN+)
EEG_CH2_VCM: R?#48.2 R?#51.2 U?#23.5(2IN+)
NetC?#12_1: C?#12.1 R?#3.1 R?#7.1 R?#8.1 R?#9.2 U?#5.1(1OUT)
NetC?#12_2: C?#12.2 R?#4.1 U?#5.2(1IN-)
NetC?#15_1: C?#15.1 R?#3.2 R?#4.2 R?#5.2
NetC?#16_1: C?#16.1 R?#12.2 R?#13.1
NetC?#16_2: C?#16.2 R?#28.2 U?#8.1(1OUT) U?#9.5(2IN+)
NetC?#17_1: C?#17.1 R?#5.1 R?#7.2 U?#6.3(IN+)
NetC?#17_2: C?#17.2 R?#8.2 ; port EEG_CH1+
NetC?#18_1: C?#18.1 R?#10.2 R?#17.1 R?#30.2
NetC?#18_2: C?#18.2 R?#15.2 R?#17.2 R?#22.2 U?#7.3(1IN+)
NetC?#19_1: C?#19.1 R?#20.2 R?#23.2 U?#6.2(IN-)
NetC?#19_2: C?#19.2 R?#16.2 ; port EEG_CH1-
NetC?#20_2: C?#20.2 R?#13.2 U?#8.3(1IN+)
NetC?#21_1: C?#21.1 R?#15.1 U?#12.7(2OUT)
NetC?#21_2: C?#21.2 R?#27.2 U?#7.2(1IN-) U?#12.6(2IN-)
NetC?#22_1: C?#22.1 C?#23.2 R?#19.2
NetC?#22_2: C?#22.2 U?#6.5(VREF) U?#10.1(OUT)
NetC?#23_1: C?#23.1 R?#14.1 U?#10.4(IN-)
NetC?#26_1: C?#26.1 R?#23.1 R?#25.2 R?#32.2
NetC?#31_1: C?#31.1 R?#9.1 R?#16.1 R?#20.1 R?#32.1 U?#11.7(2OUT)
NetC?#31_2: C?#31.2 R?#25.1 U?#11.6(2IN-)
NetC?#34_1: C?#34.1 R?#33.1 R?#37.1 R?#38.1 R?#39.2 U?#13.1(1OUT)
NetC?#34_2: C?#34.2 R?#34.1 U?#13.2(1IN-)
NetC?#37_1: C?#37.1 R?#33.2 R?#34.2 R?#35.2
NetC?#38_1: C?#38.1 R?#42.2 R?#43.1
NetC?#38_2: C?#38.2 R?#58.2 U?#16.1(1OUT) U?#17.5(2IN+)
NetC?#39_1: C?#39.1 R?#35.1 R?#37.2 U?#14.3(IN+)
NetC?#39_2: C?#39.2 R?#38.2 ; port EEG_CH2+
NetC?#40_1: C?#40.1 R?#40.2 R?#47.1 R?#60.2
NetC?#40_2: C?#40.2 R?#45.2 R?#47.2 R?#52.2 U?#15.3(1IN+)
NetC?#41_1: C?#41.1 R?#50.2 R?#53.2 U?#14.2(IN-)
NetC?#41_2: C?#41.2 R?#46.2 ; port EEG_CH2-
NetC?#42_2: C?#42.2 R?#43.2 U?#16.3(1IN+)
NetC?#43_1: C?#43.1 R?#45.1 U?#20.7(2OUT)
NetC?#43_2: C?#43.2 R?#57.2 U?#15.2(1IN-) U?#20.6(2IN-)
NetC?#44_1: C?#44.1 C?#45.2 R?#49.2
NetC?#44_2: C?#44.2 U?#14.5(VREF) U?#18.1(OUT)
NetC?#45_1: C?#45.1 R?#44.1 U?#18.4(IN-)
NetC?#48_1: C?#48.1 R?#53.1 R?#55.2 R?#62.2
NetC?#53_1: C?#53.1 R?#39.1 R?#46.1 R?#50.1 R?#62.1 U?#19.7(2OUT)
NetC?#53_2: C?#53.2 R?#55.1 U?#19.6(2IN-)
NetC?#56_1: C?#56.1 R?#63.1
NetC?#56_2: C?#56.2 R?#64.1 U?#22.1(OUT) ; port EEG_DRL
NetR?#6_1: R?#6.1 R?#10.1 R?#14.2 U?#6.6(OUT)
NetR?#6_2: R?#6.2 R?#11.2 R?#12.1
NetR?#11_1: R?#11.1 R?#27.1 R?#31.1 U?#7.1(1OUT)
NetR?#18_1: R?#18.1 U?#6.8(RG)
NetR?#21_1: R?#21.1 U?#6.1(RG)
NetR?#24_1: R?#24.1 R?#26.2 U?#9.6(2IN-)
NetR?#24_2: R?#24.2 U?#9.7(2OUT) ; port EEG_CH1
NetR?#28_1: R?#28.1 R?#29.2 U?#8.2(1IN-)
NetR?#30_1: R?#30.1 R?#31.2 U?#12.5(2IN+)
NetR?#36_1: R?#36.1 R?#40.1 R?#44.2 U?#14.6(OUT)
NetR?#36_2: R?#36.2 R?#41.2 R?#42.1
NetR?#41_1: R?#41.1 R?#57.1 R?#61.1 U?#15.1(1OUT)
NetR?#48_1: R?#48.1 U?#14.8(RG)
NetR?#51_1: R?#51.1 U?#14.1(RG)
NetR?#54_1: R?#54.1 R?#56.2 U?#17.6(2IN-)
NetR?#54_2: R?#54.2 U?#17.7(2OUT) ; port EEG_CH2
NetR?#58_1: R?#58.1 R?#59.2 U?#16.2(1IN-)
NetR?#60_1: R?#60.1 R?#61.2 U?#20.5(2IN+)
NetR?#63_2: R?#63.2 R?#64.2 R?#65.1 U?#22.4(IN-)
NetR?#65_2: R?#65.2 U?#21.1(1OUT) U?#21.2(1IN-) U?#23.6(2IN-) U?#23.7(2OUT)

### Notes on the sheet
- (near R?#62) AC-coupled/
- (near C?#54) High-Pass
- Anti-polarization
- Filter
- To configure "Anti-polarization":
  - Shorten @{"Id":"ZASXATAV\EUNOWQIK","ObjectType":2}, @{"Id":"ZASXATAV\ZSYLRQYI","ObjectType":2} (CH1) and @{"Id":"ZASXATAV\LDVCPJNR","ObjectType":2}, @{"Id":"ZASXATAV\CXKYNMVU","ObjectType":2} (CH2)
  - Remove @{"Id":"ZASXATAV\XIEPQLXJ","ObjectType":2}, @{"Id":"ZASXATAV\TRMNNTFI","ObjectType":2}, @{"Id":"ZASXATAV\BPIJAUOZ","ObjectType":2} (CH1) and @{"Id":"ZASXATAV\ARNWDVDM","ObjectType":2}, @{"Id":"ZASXATAV\CLJQQSED","ObjectType":2}, @{"Id":"ZASXATAV\HUWLBNUI","ObjectType":2} (CH2)
  To configure "AC-coupled":
  - Remove @{"Id":"ZASXATAV\DEMCHMGK","ObjectType":2}, @{"Id":"ZASXATAV\FORZWMRQ","ObjectType":2}

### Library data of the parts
C?#12 C?#31 C?#34 C?#53 = 885012105018: 0402 10nF 25V; Manufacturer: Wurth Elektronik; Match Code: WCAP-CSGP; Case/Size Code: 0402; Capacitance Tolerance: +/-20%; Ceramic Type: X5R; Dissipation Factor: 10%; Insulation Resistance: 5GΩ; Technical Reference: X5R0402104M025DFCT10000
C?#13 C?#14 C?#24 C?#25 C?#27-C?#30 C?#32 C?#33 C?#35 C?#36 C?#46 C?#47 C?#49-C?#52 C?#54 C?#55 C?#57-C?#60 = 0106031041050: as C?#2 on sheet Power Supplies
C?#15 C?#22 C?#23 C?#26 C?#37 C?#44 C?#45 C?#48 = 885012108020: 25V 33uF X5R ±20% 1206 Multilayer Ceramic Capacitors MLCC - SMD/SMT ROHS; Manufacturer: Wurth Elektronik; Match Code: WCAP-CSGP; Case/Size Code: 1206; Capacitance Tolerance: +/-20%; Dissipation Factor: 7%; Insulation Resistance: 0.1GΩ; Technical Reference: X5R1206475M025DFCT10000
C?#16 C?#20 C?#38 C?#42 = 885012210006: WCAP-CSGP Multilayer Ceramic Chip Capacitor, General Purpose, size 1812, X7R, 10nF, 25V; Manufacturer: Wurth Elektronik; Case/Size Code: 1812; Capacitance Tolerance: +/-10%; Dissipation Factor: 3.5%; Insulation Resistance: 10GΩ; Technical Reference: X7R1812103K025DFCT10000
C?#17 C?#19 C?#39 C?#41 C?#56 = 0106031051050: as C?#9 on sheet Power Supplies
C?#18 C?#21 C?#40 C?#43 = 885012105017: WCAP-CSGP Multilayer Ceramic Chip Capacitor, General Purpose, size 0402, X5R, 220nF, 16V; Manufacturer: Wurth Elektronik; Case/Size Code: 0402; Capacitance Tolerance: +/-20%; Dissipation Factor: 10%; Insulation Resistance: 0.5GΩ; Technical Reference: X5R0402224M016DFCT10000
R?#3 R?#7 R?#8 R?#16 R?#20 R?#32 R?#33 R?#37 R?#38 R?#46 R?#50 R?#62 = Resistor 4.87 MOhm 0402 1%: 4.87 MOhms ±1% 0.063W, 1/16W Chip Resistor 0402 (1005 Metric) Moisture Resistant Thick Film
R?#4 R?#25 R?#34 R?#55 = Resistor 3.16 MOhm 0402 1%: 3.16 MOhms ±1% 0.063W, 1/16W Chip Resistor 0402 (1005 Metric) Automotive AEC-Q200 Thick Film
R?#5 R?#23 R?#35 R?#53 = Resistor 48.7 KOhm 0402 1%: 48.7 kOhms ±1% 0.063W, 1/16W Chip Resistor 0402 (1005 Metric) Automotive AEC-Q200, Moisture Resistant Thick Film
R?#6 R?#9-R?#11 R?#36 R?#39-R?#41 = Resistor 0 Ohm 0402: 0 Ohms Jumper Chip Resistor 0402 (1005 Metric) Moisture Resistant Thick Film
R?#12 R?#42 = Resistor 4.22 KOhm 0402 1%: 4.22 kOhms ±1% 0.1W, 1/10W Chip Resistor 0402 (1005 Metric) Automotive AEC-Q200 Thick Film
R?#13 R?#43 = Resistor 60.4 KOhm 0402 1%: 60.4 kOhms ±1% 0.063W, 1/16W Chip Resistor 0402 (1005 Metric) Moisture Resistant Thick Film
R?#14 R?#44 = Resistor 138 KOhm 0402 1%: 138 kOhms ±1% 0.1W, 1/10W Chip Resistor 0402 (1005 Metric) Automotive AEC-Q200, Moisture Resistant Thin Film
R?#15 R?#27 R?#30 R?#31 R?#45 R?#57 R?#60 R?#61 = Resistor 14.5 KOhm 0402 0.5%: 14.5 kOhms ±0.5% 0.063W, 1/16W Chip Resistor 0402 (1005 Metric) Thin Film
R?#17 R?#22 R?#47 R?#52 = Resistor 2.87 MOhm 0402 1%: 2.87 MOhms ±1% 0.063W, 1/16W Chip Resistor 0402 (1005 Metric) Automotive AEC-Q200 Thick Film
R?#18 R?#21 R?#48 R?#51 = Resistor 255 Ohm 0402 1%: 255 Ohms ±1% 0.1W, 1/10W Chip Resistor 0402 (1005 Metric) Automotive AEC-Q200 Thick Film
R?#19 R?#49 = Resistor 54.9 KOhm 0402 1%: 138 kOhms ±1% 0.1W, 1/10W Chip Resistor 0402 (1005 Metric) Automotive AEC-Q200, Moisture Resistant Thin Film
R?#24 R?#54 = Resistor 150 KOhm 0402 1%: Code 1503 ,1/16W 1%
R?#26 R?#29 R?#56 R?#59 R?#63 R?#65 = Resistor 10 KOhm 0402 1%: Code 103, 1/16W 1%
R?#28 R?#58 = Resistor 100 KOhm 0402 1%: Code 104, 1/16W 1%
R?#64 = Resistor 1 MOhm 0402 1%_1: Code 105, 1/16W 1%
U?#5 U?#7-U?#9 U?#11-U?#13 U?#15-U?#17 U?#19-U?#21 U?#23 = OPA2735AIDR: 0.05μV/°C max, Single-Supply CMOS Operational Amplifiers Zero-drift Series
U?#6 U?#14 = INA128UA/2K5: Precision, Low Power Instrumentation Amplifiers
U?#10 U?#18 U?#22 = OPA735AIDBVR: Zero-Drift Amplifier 1 Circuit Rail-to-Rail SOT-23-5; Mfr_Name: Texas Instruments

## Sheet ADC.SchDoc: EEG Measurement Circuit
size A2; Date: 24/01/2025; DrawnBy: Giang Phan Truong; SheetNumber: 5; SheetTotal: 7
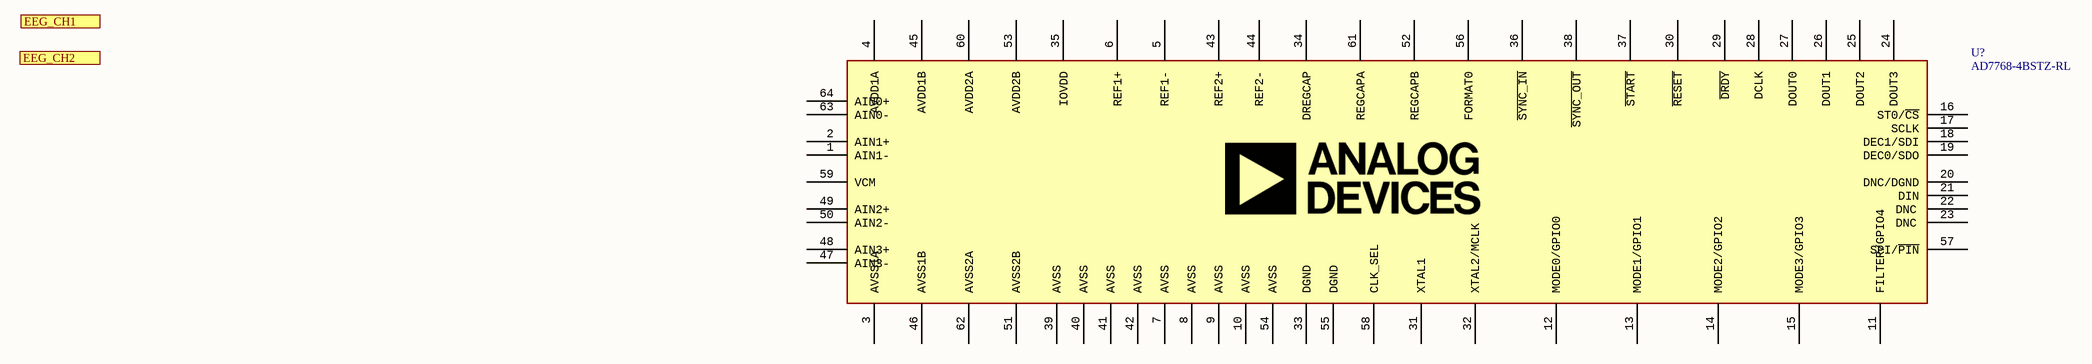
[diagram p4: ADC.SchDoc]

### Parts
(Parts that share a designator on the sheet are numbered #1, #2 ... from top to bottom, then left to right.)
U?#24  value AD7768-4BSTZ-RL  [ST-64-2_ADI]  (hidden comment: 24 Bit Analog to Digital Converter 4 Input 4 Sigma-Delta)

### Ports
EEG_CH1 (out, see Block Diagram[4B], EEG Preprocessing[8A]), EEG_CH2 (out, see Block Diagram[4B], EEG Preprocessing[8C])

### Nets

Not connected (* = marked no-connect by the designer): U?#24 1(AIN1-) 2(AIN1+) 3(AVSS1A) 4(AVDD1A) 5(REF1-) 6(REF1+) 7(AVSS) 8(AVSS) 9(AVSS) 10(AVSS) 11(FILTER/GPIO4) 12(MODE0/GPIO0) 13(MODE1/GPIO1) 14(MODE2/GPIO2) 15(MODE3/GPIO3) 16(ST0/~{CS}) 17(SCLK) 18(DEC1/SDI) 19(DEC0/SDO) 20(DNC/DGND) 21(DIN) 22(DNC) 23(DNC) 24(DOUT3) 25(DOUT2) 26(DOUT1) 27(DOUT0) 28(DCLK) 29(~{DRDY}) 30(~{RESET}) 31(XTAL1) 32(XTAL2/MCLK) 33(DGND) 34(DREGCAP) 35(IOVDD) 36(~{SYNC_IN}) 37(~{START}) 38(~{SYNC_OUT}) 39(AVSS) 40(AVSS) 41(AVSS) 42(AVSS) 43(REF2+) 44(REF2-) 45(AVDD1B) 46(AVSS1B) 47(AIN3-) 48(AIN3+) 49(AIN2+) 50(AIN2-) 51(AVSS2B) 52(REGCAPB) 53(AVDD2B) 54(AVSS) 55(DGND) 56(FORMAT0) 57(SPI/~{PIN}) 58(CLK_SEL) 59(VCM) 60(AVDD2A) 61(REGCAPA) 62(AVSS2A) 63(AIN0-) 64(AIN0+)

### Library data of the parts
U?#24 = AD7768-4BSTZ-RL: 24 Bit Analog to Digital Converter 4 Input 4 Sigma-Delta 64-LQFP (10x10); Mfr_Name: Analog Devices Inc

## Sheet Digital Processing.SchDoc: EEG Measurement Circuit
size A3; Date: 24/01/2025; DrawnBy: Giang Phan Truong; SheetNumber: 7; SheetTotal: 8

## Sheet Interface.SchDoc: EEG Measurement Circuit
size A3; Date: 24/01/2025; DrawnBy: Giang Phan Truong; SheetNumber: 7; SheetTotal: 7
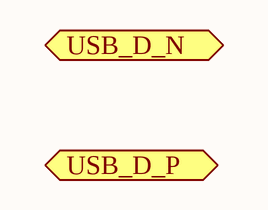
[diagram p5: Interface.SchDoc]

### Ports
USB_D_N (bidir, see Block Diagram[7B], Power Supplies[2A]), USB_D_P (bidir, see Block Diagram[7B], Power Supplies[2A])

## Sheet Patient Protection.SchDoc: EEG Measurement Circuit
size A3; Date: 24/01/2025; DrawnBy: Giang Phan Truong; SheetNumber: 3; SheetTotal: 7
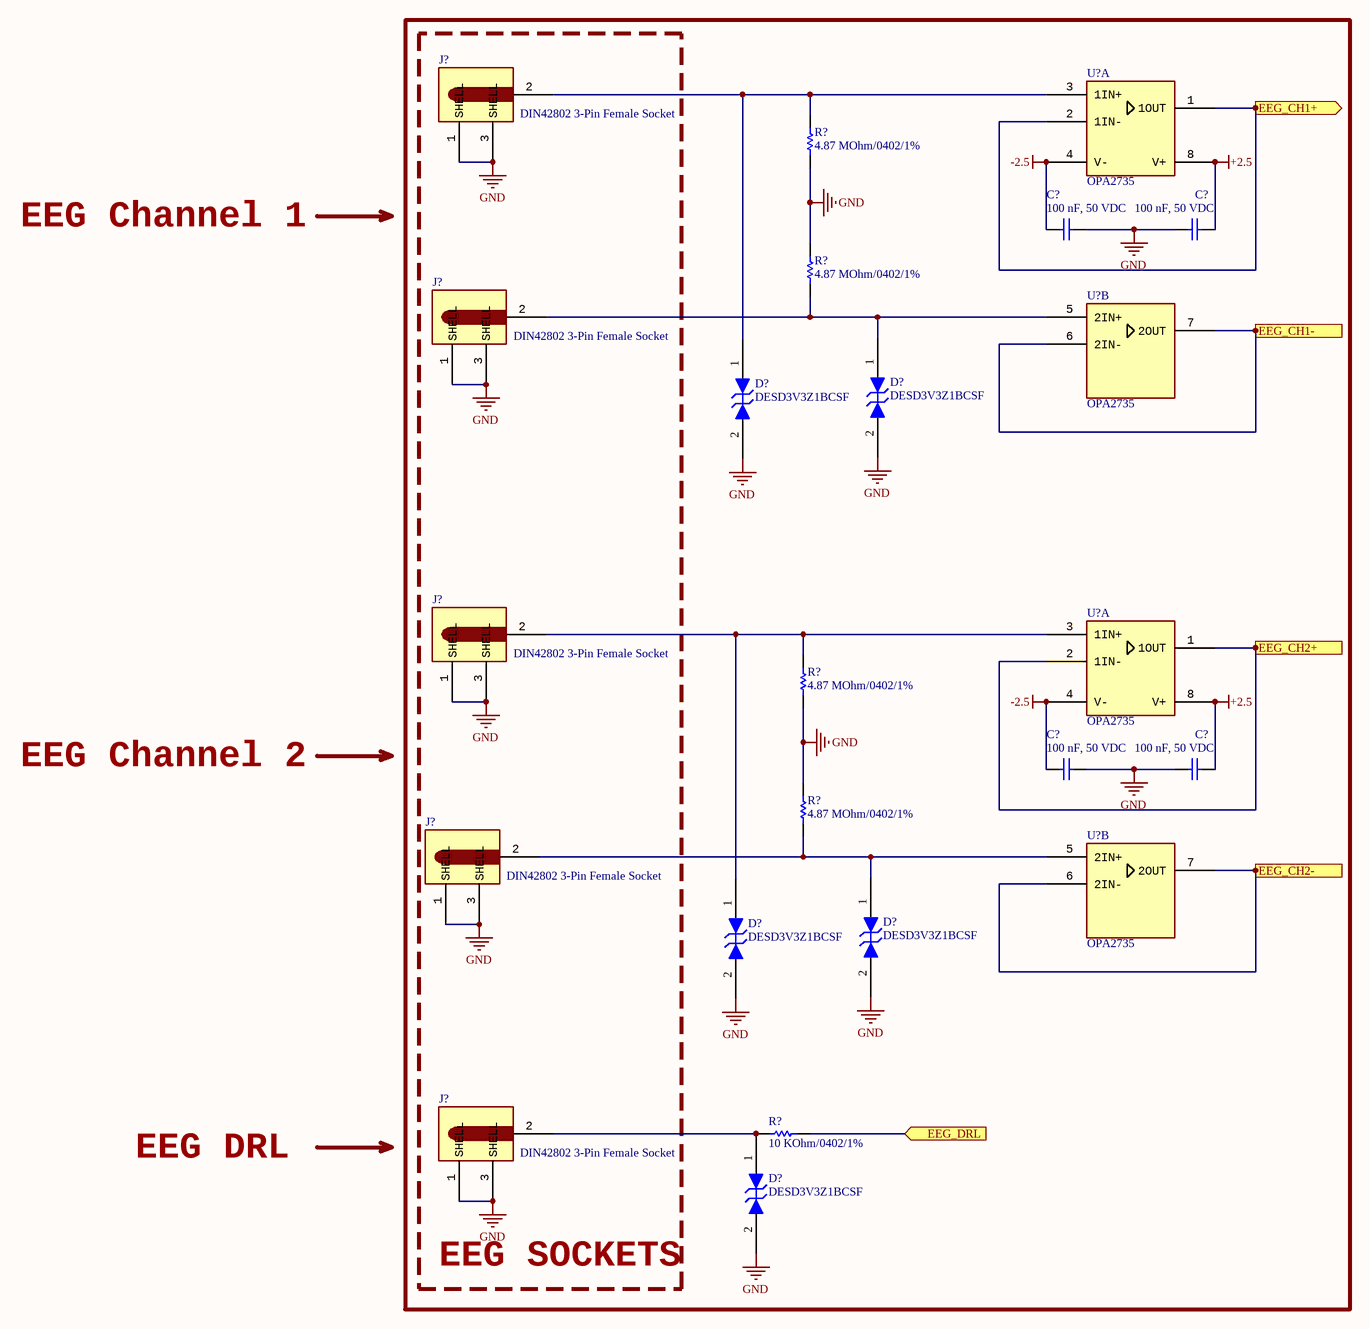
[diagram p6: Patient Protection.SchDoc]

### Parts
(Parts that share a designator on the sheet are numbered #1, #2 ... from top to bottom, then left to right.)
C?#61  100 nF, 50 VDC  [CAP_0603]
C?#62  100 nF, 50 VDC  [CAP_0603]
C?#63  100 nF, 50 VDC  [CAP_0603]
C?#64  100 nF, 50 VDC  [CAP_0603]
D?#1  DESD3V3Z1BCSF  [X2-DSN0603-2]
D?#2  DESD3V3Z1BCSF  [X2-DSN0603-2]
D?#3  DESD3V3Z1BCSF  [X2-DSN0603-2]
D?#4  DESD3V3Z1BCSF  [X2-DSN0603-2]
D?#5  DESD3V3Z1BCSF  [X2-DSN0603-2]
J?#2  value DIN42802 3-Pin Female Socket  [DIN42802-1.5MM SOCKET]  (hidden comment: DIN42802 1.5mm)
J?#3  value DIN42802 3-Pin Female Socket  [DIN42802-1.5MM SOCKET]  (hidden comment: DIN42802 1.5mm)
J?#4  value DIN42802 3-Pin Female Socket  [DIN42802-1.5MM SOCKET]  (hidden comment: DIN42802 1.5mm)
J?#5  value DIN42802 3-Pin Female Socket  [DIN42802-1.5MM SOCKET]  (hidden comment: DIN42802 1.5mm)
J?#6  value DIN42802 3-Pin Female Socket  [DIN42802-1.5MM SOCKET]  (hidden comment: DIN42802 1.5mm)
R?#66  value 4.87 MOhm/0402/1%  [R0402]  (hidden comment: Resistor 4.87 MOhm 0402 1%)
R?#67  value 4.87 MOhm/0402/1%  [R0402]  (hidden comment: Resistor 4.87 MOhm 0402 1%)
R?#68  value 4.87 MOhm/0402/1%  [R0402]  (hidden comment: Resistor 4.87 MOhm 0402 1%)
R?#69  value 4.87 MOhm/0402/1%  [R0402]  (hidden comment: Resistor 4.87 MOhm 0402 1%)
R?#70  value 10 KOhm/0402/1%  [R0402]  (hidden comment: Resistor 10 KOhm 0402 1%)
U?#25  value OPA2735  [SOIC-8]  (hidden comment: OPA2735AIDR)  (part A of 2)
U?#26  value OPA2735  [SOIC-8]  (hidden comment: OPA2735AIDR)  (part B of 2)
U?#27  value OPA2735  [SOIC-8]  (hidden comment: OPA2735AIDR)  (part A of 2)
U?#28  value OPA2735  [SOIC-8]  (hidden comment: OPA2735AIDR)  (part B of 2)

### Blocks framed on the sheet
EEG SOCKETS: J?#2-J?#6

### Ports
EEG_CH1+ (out, see Block Diagram[3B], EEG Preprocessing[1A]), EEG_CH1- (out, see Block Diagram[3B], EEG Preprocessing[1A]), EEG_CH2+ (out, see Block Diagram[3B], EEG Preprocessing[1C]), EEG_CH2- (out, see Block Diagram[3B], EEG Preprocessing[1C]), EEG_DRL (in, see Block Diagram[3B], EEG Preprocessing[1D])

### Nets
+2.5: C?#62.1 C?#64.1 U?#25.8(V+) U?#27.8(V+)
-2.5: C?#61.2 C?#63.2 U?#25.4(V-) U?#27.4(V-)
GND: C?#61.1 C?#62.2 C?#63.1 C?#64.2 D?#1.2 D?#2.2 D?#3.2 D?#4.2 D?#5.2 J?#2.1(SHELL) J?#2.3(SHELL) J?#3.1(SHELL) J?#3.3(SHELL) J?#4.1(SHELL) J?#4.3(SHELL) J?#5.1(SHELL) J?#5.3(SHELL) J?#6.1(SHELL) J?#6.3(SHELL) R?#66.1 R?#67.2 R?#68.1 R?#69.2
NetC?#17_2: U?#25.1(1OUT) U?#25.2(1IN-) ; port EEG_CH1+
NetC?#19_2: U?#26.6(2IN-) U?#26.7(2OUT) ; port EEG_CH1-
NetC?#39_2: U?#27.1(1OUT) U?#27.2(1IN-) ; port EEG_CH2+
NetC?#41_2: U?#28.6(2IN-) U?#28.7(2OUT) ; port EEG_CH2-
NetC?#56_2: R?#70.2 ; port EEG_DRL
NetD?#1_1: D?#1.1 J?#2.2(PORT) R?#66.2 U?#25.3(1IN+)
NetD?#2_1: D?#2.1 J?#3.2(PORT) R?#67.1 U?#26.5(2IN+)
NetD?#3_1: D?#3.1 J?#4.2(PORT) R?#68.2 U?#27.3(1IN+)
NetD?#4_1: D?#4.1 J?#5.2(PORT) R?#69.1 U?#28.5(2IN+)
NetD?#5_1: D?#5.1 J?#6.2(PORT) R?#70.1

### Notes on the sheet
- EEG Channel 1
- EEG Channel 2
- EEG DRL

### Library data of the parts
C?#61-C?#64 = 0106031041050: as C?#2 on sheet Power Supplies
D?#1-D?#5 = DESD3V3Z1BCSF: LOW CAPACITANCE BIDIRECTIONAL TVS DIODE
J?#2-J?#6 = DIN42802 1.5mm: 3 PIN Socket Female Socket for PCB EEG EMG DIN42802 1.5 mm Connector
R?#66-R?#69 = Resistor 4.87 MOhm 0402 1%: as R?#3 on sheet EEG Preprocessing
R?#70 = Resistor 10 KOhm 0402 1%: Code 103, 1/16W 1%
U?#25-U?#28 = OPA2735AIDR: as U?#5 on sheet EEG Preprocessing

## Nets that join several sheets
+2.5: Power Supplies (C?#10.2 SB?#3.1 U?#4.2), EEG Preprocessing (24 pins), Patient Protection (C?#62.1 C?#64.1 U?#25.8 U?#27.8)
-2.5: Power Supplies (SB?#4.1), EEG Preprocessing (24 pins), Patient Protection (C?#61.2 C?#63.2 U?#25.4 U?#27.4)
GND: Power Supplies (12 pins), EEG Preprocessing (45 pins), Patient Protection (23 pins)
NetC?#17_2: EEG Preprocessing (C?#17.2 R?#8.2), Patient Protection (U?#25.1 U?#25.2)
NetC?#19_2: EEG Preprocessing (C?#19.2 R?#16.2), Patient Protection (U?#26.6 U?#26.7)
NetC?#39_2: EEG Preprocessing (C?#39.2 R?#38.2), Patient Protection (U?#27.1 U?#27.2)
NetC?#41_2: EEG Preprocessing (C?#41.2 R?#46.2), Patient Protection (U?#28.6 U?#28.7)
NetC?#56_2: EEG Preprocessing (C?#56.2 R?#64.1 U?#22.1), Patient Protection (R?#70.2)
